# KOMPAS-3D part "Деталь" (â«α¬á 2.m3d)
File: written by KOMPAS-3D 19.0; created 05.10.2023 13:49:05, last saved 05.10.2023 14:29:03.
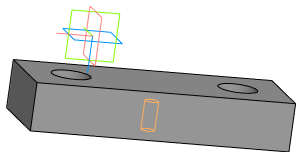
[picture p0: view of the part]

Document properties: Автор: admin; Организация: Hewlett-Packard Company; Полное имя файла: C:\Users\Petrenko-VE\Documents\Горка_2.m3d

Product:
- Part/product: Деталь
    Масса: 9.53603
  - Body: Тело 1
      Масса: 25.3345

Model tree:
1. Эскиз:1
2. Элемент выдавливания:1
     Расстояние 1 = 80
3. Эскиз:2  (with: Элемент выдавливания:1)
4. Элемент выдавливания:2
     Расстояние 2 = 80
5. Эскиз:3  (with: Элемент выдавливания:1)
6. Элемент выдавливания:3
     Расстояние 2 = 6
7. Эскиз:4  (with: Элемент выдавливания:1, Элемент выдавливания:2, Элемент выдавливания:3)
8. Элемент выдавливания:4
     Расстояние 2 = 80
9. Эскиз:5  (with: Элемент выдавливания:1, Элемент выдавливания:3, Элемент выдавливания:4)
10. Элемент выдавливания:5
     Расстояние 2 = 80
11. Эскиз:6  (with: Элемент выдавливания:1, Элемент выдавливания:5)
12. Элемент выдавливания:6
     Расстояние 2 = 80
13. Эскиз:7  (with: Элемент выдавливания:1, Элемент выдавливания:5)
14. Элемент выдавливания:7
     Расстояние 2 = 80
15. Эскиз:8  (with: Элемент выдавливания:1, Элемент выдавливания:3)
16. Элемент выдавливания:8
     Расстояние 2 = 80
17. Эскиз:9  (with: Элемент выдавливания:1, Элемент выдавливания:2)
18. Элемент выдавливания:9
     Расстояние 2 = 80
19. Эскиз:10  (with: Элемент выдавливания:1, Элемент выдавливания:9)
20. Элемент выдавливания:10
     Расстояние 2 = 40
21. Эскиз:11  (with: Элемент выдавливания:1, Элемент выдавливания:3)
22. Элемент выдавливания:11
     Расстояние 2 = 80
23. Эскиз:12  (with: Элемент выдавливания:1, Элемент выдавливания:8)
24. Элемент выдавливания:12
     Расстояние 2 = 30
25. Условное изображение резьбы:2  (with: Элемент выдавливания:12)  (labels: M14; cil0_24705-2004 coarse)
     Длина резьбы = 30; Шаг резьбы = 2; Номинальный диаметр резьбы = 14
26. Подгонка:2  (with: Элемент выдавливания:12)
27. Эскиз:14  (with: Элемент выдавливания:8)
28. Элемент выдавливания:14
